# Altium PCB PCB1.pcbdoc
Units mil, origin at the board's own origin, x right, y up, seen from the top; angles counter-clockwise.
Board outline 2566.1 x 2465 mil, 4 copper layers (Top Layer, Inner1, Inner2, Bottom Layer); 31 components, 17 nets, 97 pads, 94 vias.
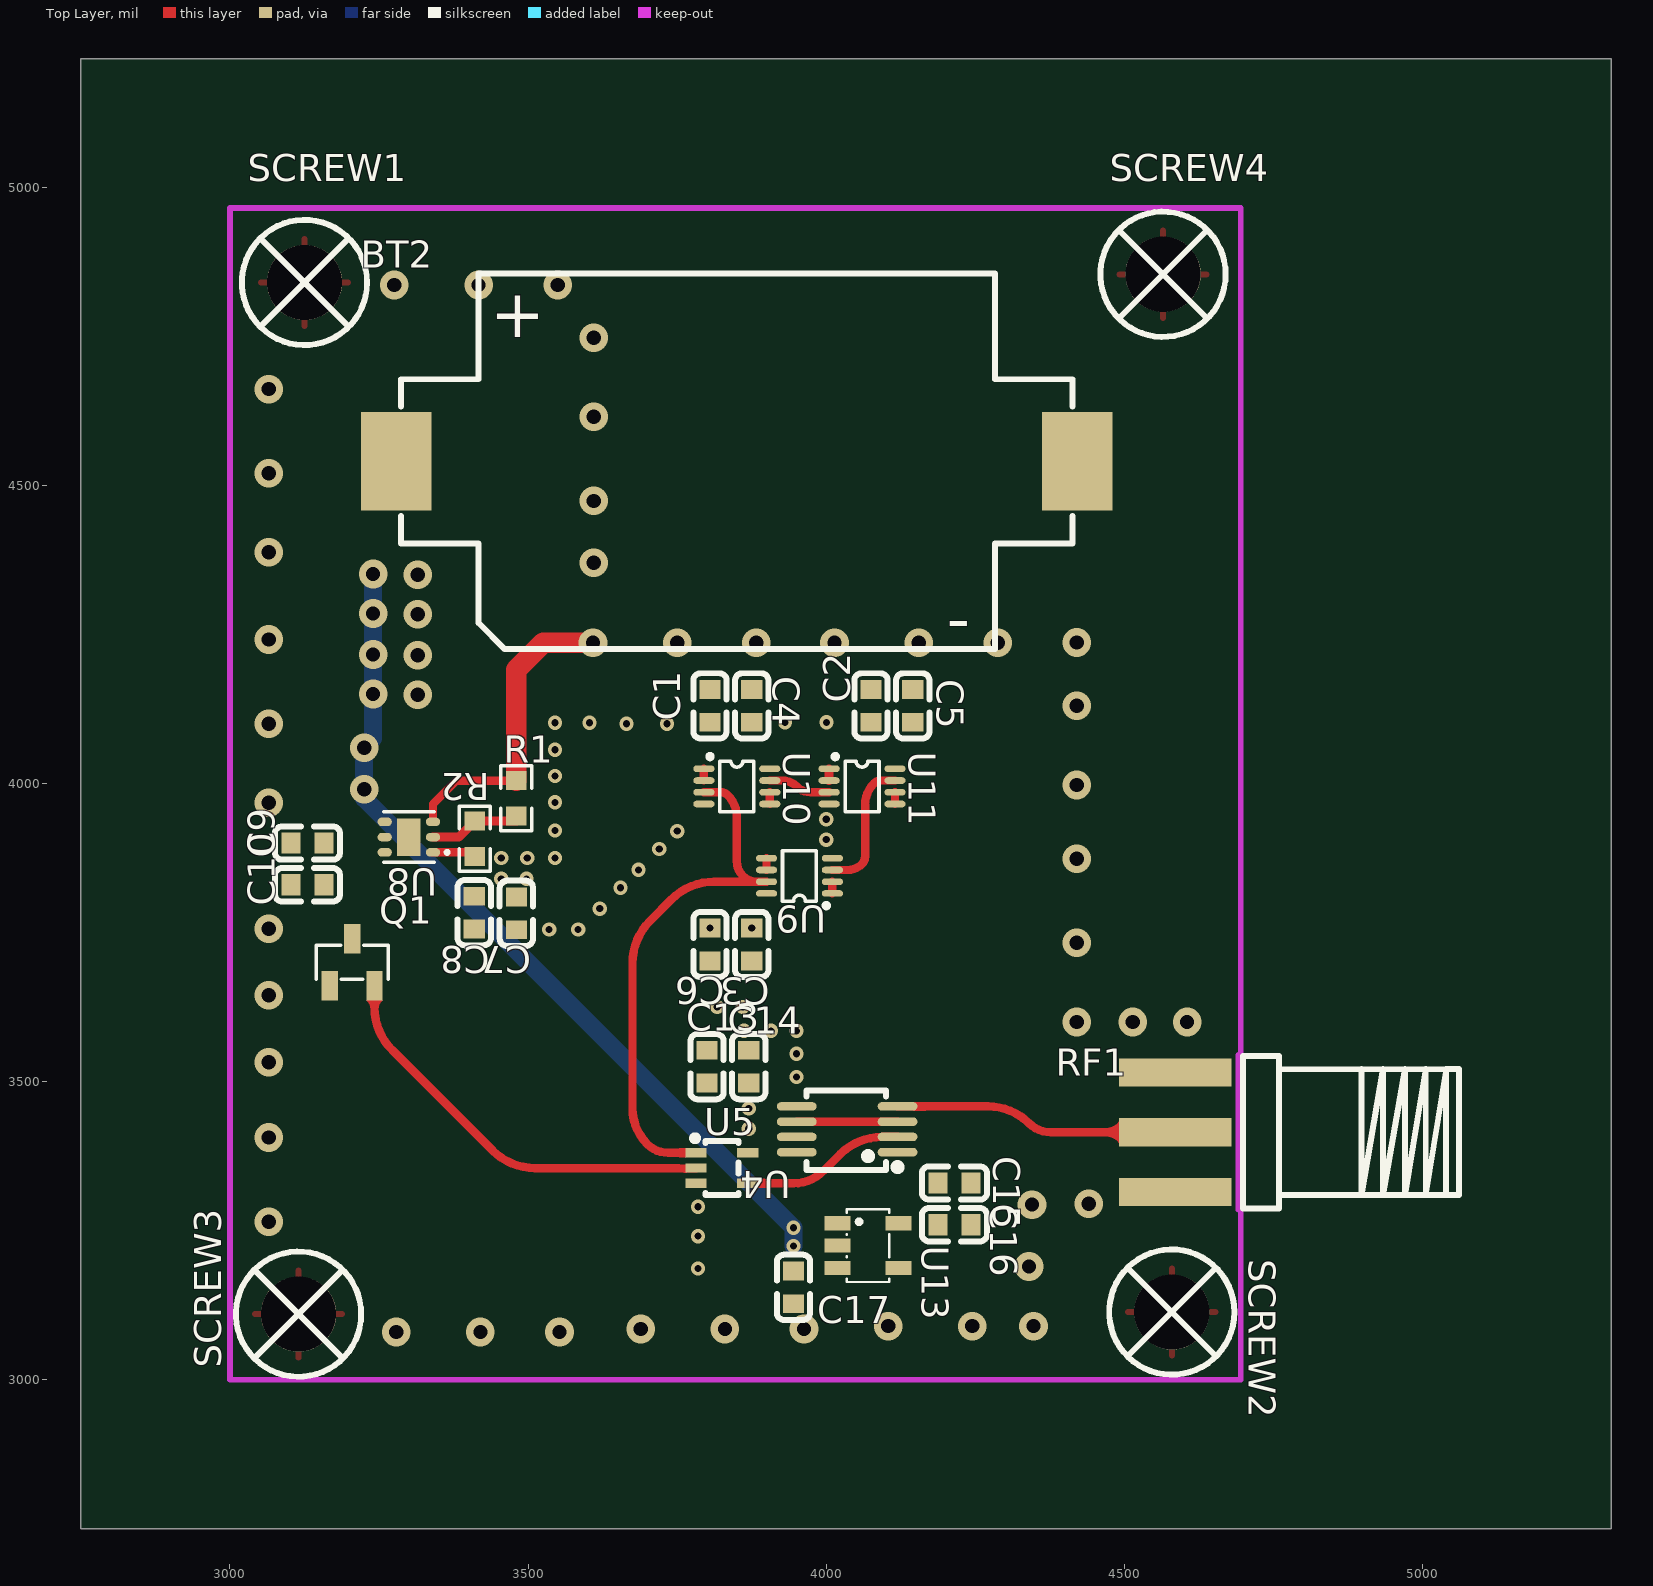
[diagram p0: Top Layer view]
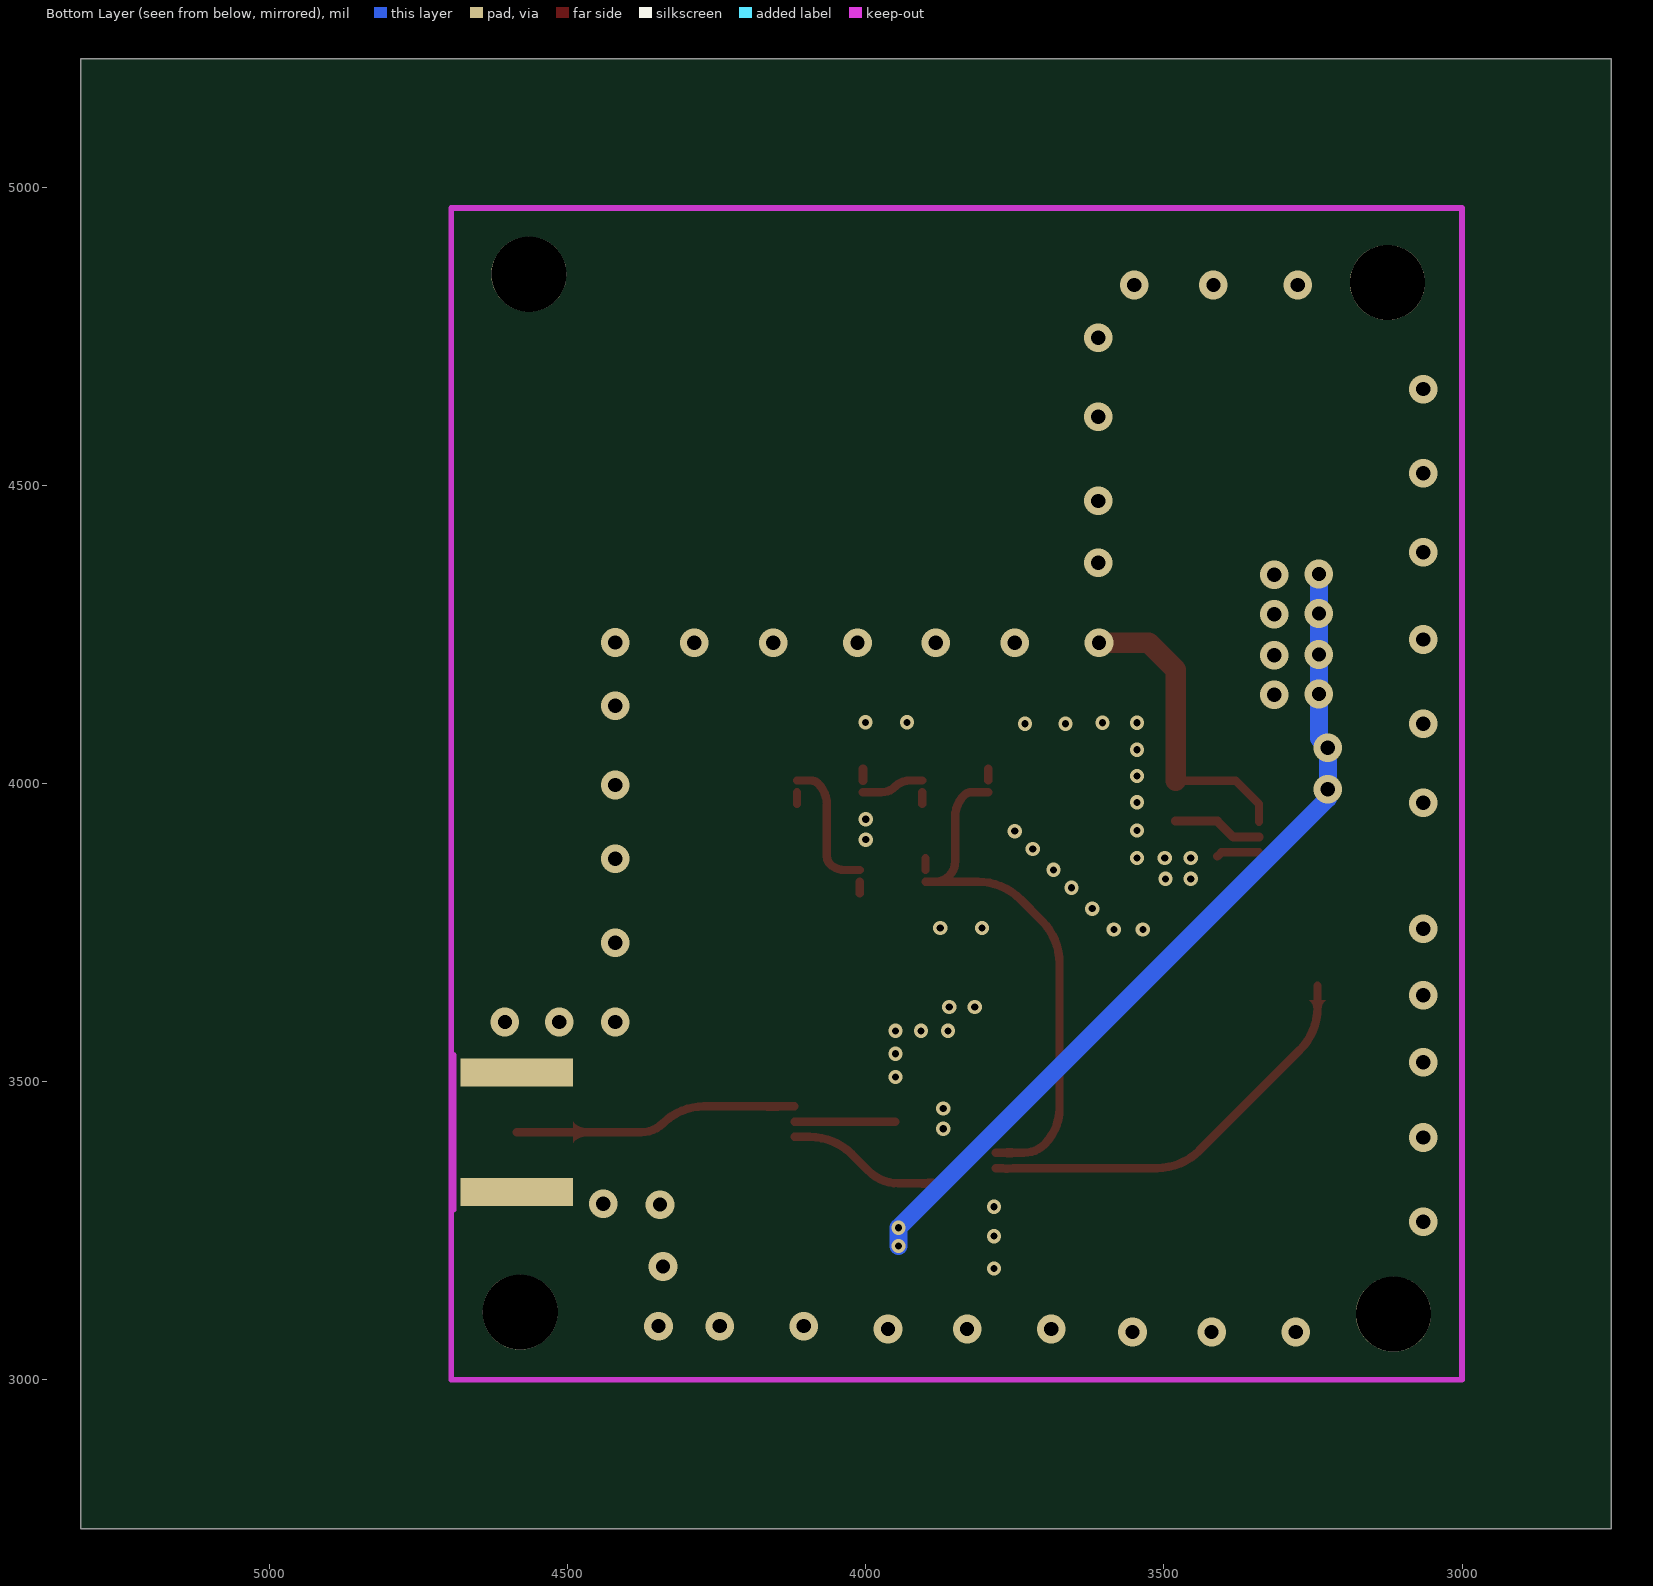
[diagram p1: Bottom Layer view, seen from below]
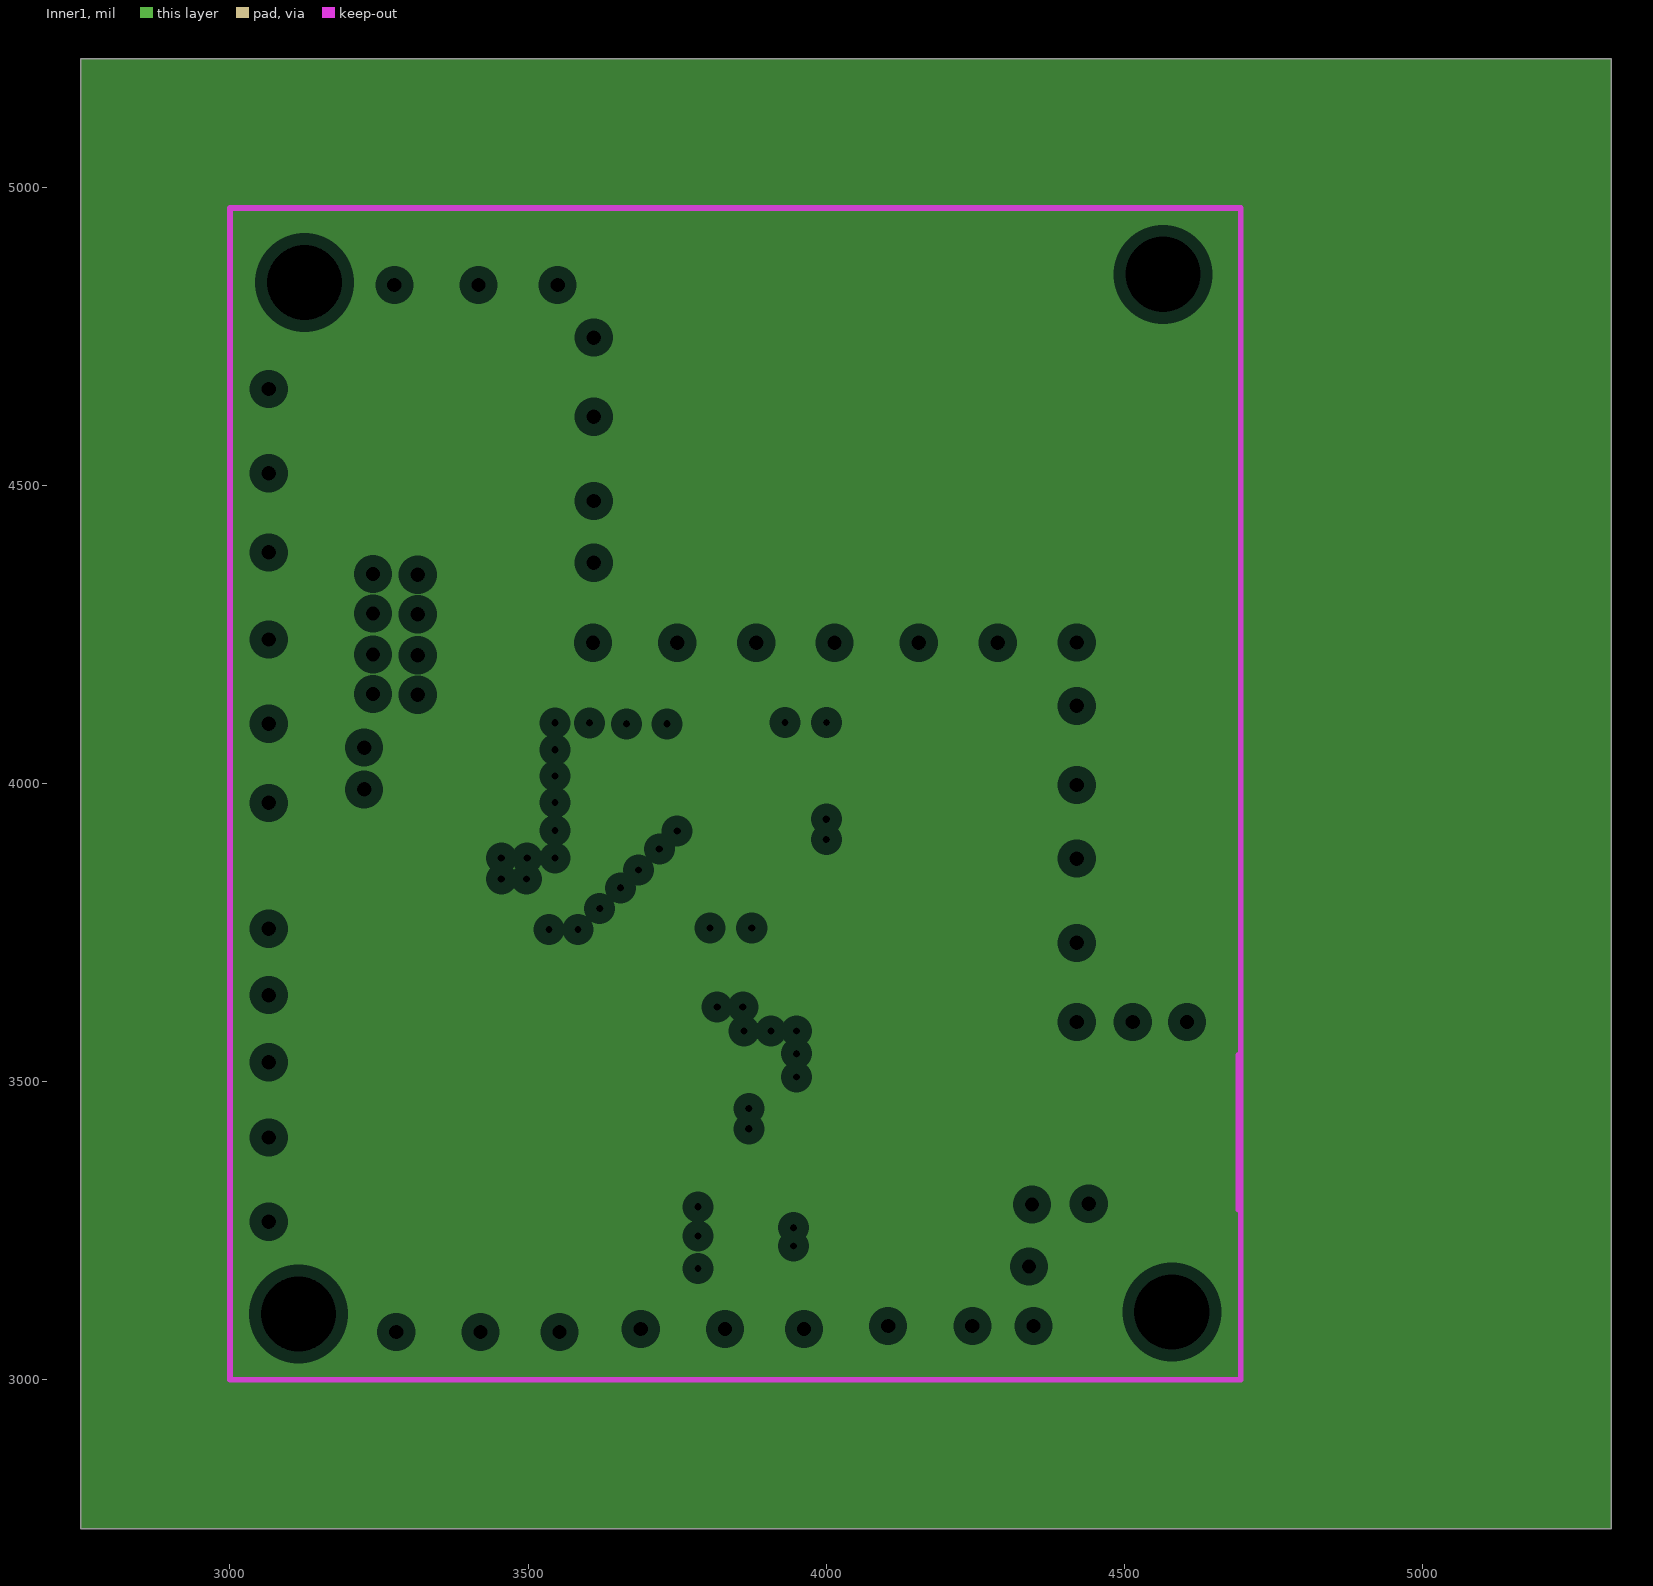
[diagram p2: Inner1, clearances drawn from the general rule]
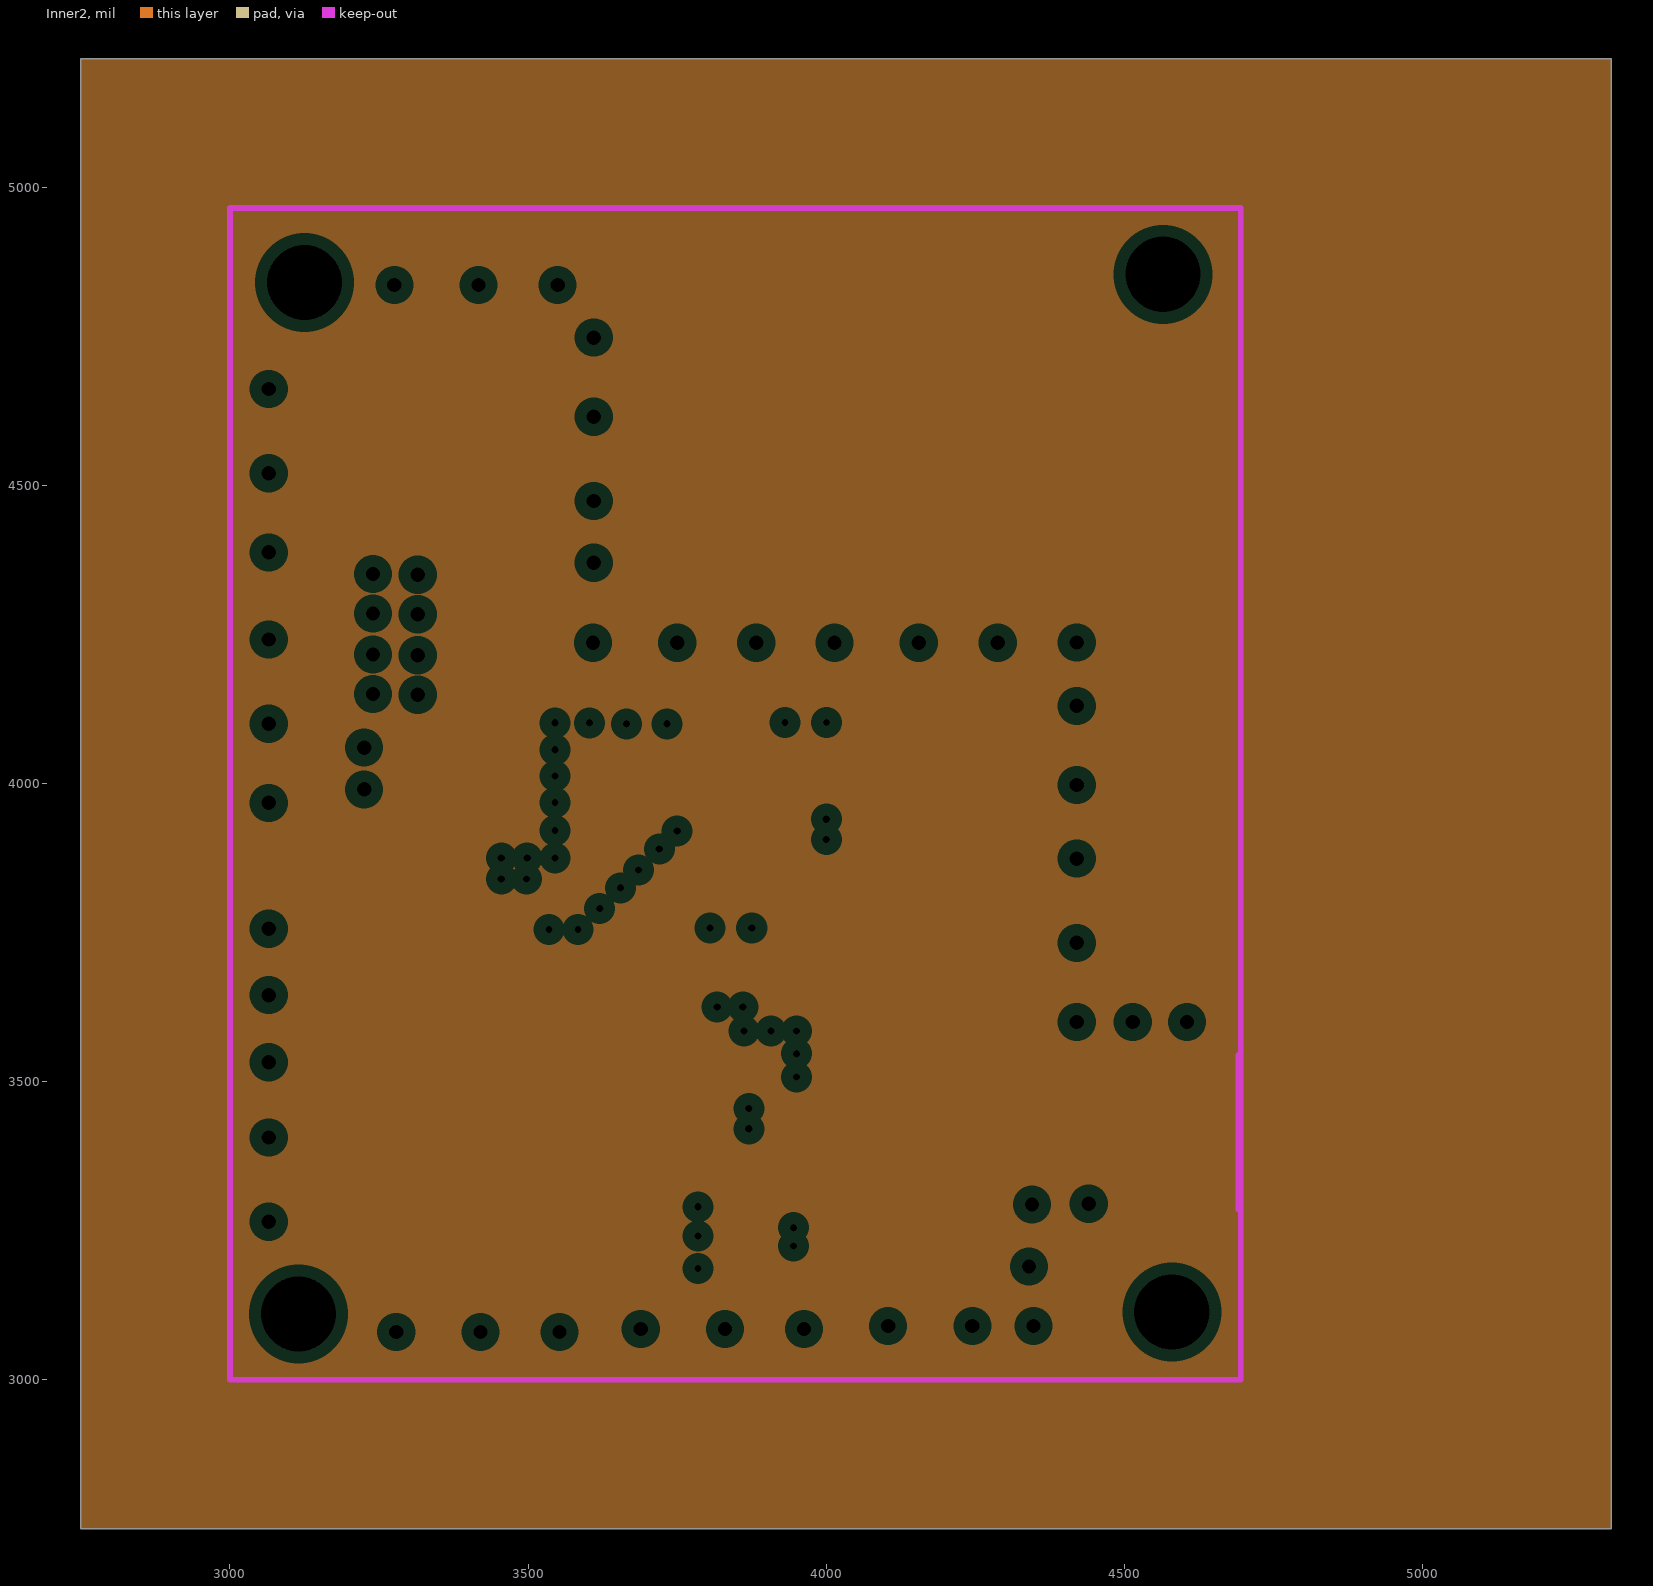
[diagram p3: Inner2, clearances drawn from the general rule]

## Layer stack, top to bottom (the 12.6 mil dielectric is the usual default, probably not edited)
Top Layer: signal copper (thickness not stored)
Dielectric: dielectric 12.6, FR-4, Dk 4.8
Inner1: plane copper (thickness not stored)
Dielectric: dielectric 12.6, FR-4, Dk 4.8
Inner2: plane copper (thickness not stored)
Dielectric: dielectric 12.6, FR-4, Dk 4.8
Bottom Layer: signal copper (thickness not stored)

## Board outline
5316.1,2750 2750,2750 2750,5215 5316.1,5215

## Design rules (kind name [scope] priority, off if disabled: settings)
BoardOutlineClearance copperThickness1oz [All] p0: genericclearance=10 ignorepadtopadclearanceinfootprint=FALSE except(0: Arc-SplitContinuation Track-SplitContinuation SMDPad-SplitContinuation THPad-SplitContinuation Via-SplitContinuation Fill-SplitContinuation Poly-SplitContinuation Region-SplitContinuation Text-SplitContinuation; 6: Track-CutoutEdge SMDPad-CutoutEdge THPad-CutoutEdge Via-CutoutEdge Region-CutoutEdge; 11.8: Track-OutlineEdge SMDPad-OutlineEdge THPad-OutlineEdge Via-OutlineEdge Fill-OutlineEdge Region-OutlineEdge Poly-OutlineEdge Text-OutlineEdge Fill-CutoutEdge)
BoardOutlineClearance copperThickness2oz [All] p0: genericclearance=10 ignorepadtopadclearanceinfootprint=FALSE except(0: Arc-SplitContinuation Track-SplitContinuation SMDPad-SplitContinuation THPad-SplitContinuation Via-SplitContinuation Fill-SplitContinuation Poly-SplitContinuation Region-SplitContinuation Text-SplitContinuation; 6: Track-CutoutEdge SMDPad-CutoutEdge THPad-CutoutEdge Via-CutoutEdge Region-CutoutEdge; 11.8: Track-OutlineEdge SMDPad-OutlineEdge THPad-OutlineEdge Via-OutlineEdge Fill-OutlineEdge Region-OutlineEdge Poly-OutlineEdge Text-OutlineEdge Fill-CutoutEdge)
Clearance copperThickness1oz [(InNet('+3V') OR InNet('GND') OR InNet('$1N1794') OR InNet('$1N1799') OR InNet('$1N1813') OR InNet('$1N1833') OR InNet('$1N1818') OR InNet('$1N1779') OR InNet('$1N1783') OR InNet('VCC') OR InNet('$1N2427') OR InNet('$1N2685') OR InNet('$1N2734') OR InNet('$1N2854') OR InNet('$1N5148') OR InNet('$1N5155') OR InNet('$1N5582'))] p1: gap=7 ignorepadtopadclearanceinfootprint=FALSE except(4: Track-Track; 6: Track-SMDPad SMDPad-SMDPad Track-THPad SMDPad-THPad THPad-THPad Track-Via SMDPad-Via THPad-Via Via-Via SMDPad-Fill THPad-Fill Via-Fill Fill-Fill Track-Region SMDPad-Region THPad-Region Via-Region Region-Region Track-Poly SMDPad-Poly THPad-Poly Via-Poly Fill-Poly Region-Poly Poly-Poly Track-Text SMDPad-Text THPad-Text Via-Text Fill-Text Region-Text Poly-Text Text-Text; 6.9: Track-Hole SMDPad-Hole THPad-Hole Via-Hole Fill-Hole Region-Hole Poly-Hole Text-Hole Sheet-Hole; 11.8: Track-Fill Fill-Region Track-Sheet SMDPad-Sheet THPad-Sheet Via-Sheet Fill-Sheet Region-Sheet Poly-Sheet Text-Sheet)
Clearance copperThickness2oz [All] p1: gap=7 ignorepadtopadclearanceinfootprint=FALSE except(6: Track-SMDPad SMDPad-SMDPad Track-THPad SMDPad-THPad THPad-THPad Track-Via SMDPad-Via THPad-Via Via-Via SMDPad-Fill THPad-Fill Via-Fill Fill-Fill Track-Region SMDPad-Region THPad-Region Via-Region Region-Region Track-Poly SMDPad-Poly THPad-Poly Via-Poly Fill-Poly Region-Poly Poly-Poly Track-Text SMDPad-Text THPad-Text Via-Text Fill-Text Region-Text Poly-Text Text-Text; 6.9: Track-Hole SMDPad-Hole THPad-Hole Via-Hole Fill-Hole Region-Hole Poly-Hole Text-Hole Sheet-Hole; 8: Track-Track; 11.8: Track-Fill Fill-Region Track-Sheet SMDPad-Sheet THPad-Sheet Via-Sheet Fill-Sheet Region-Sheet Poly-Sheet Text-Sheet)
DiffPairsRouting differentialPair [All] p1: maxuncoupledlength=10 minlimit=5.9843 maxlimit=5.9843 mostfreqgap=5.9843 toplayer_minwidth=5 toplayer_prefwidth=10 toplayer_maxwidth=100 bottomlayer_minwidth=5 bottomlayer_prefwidth=10 bottomlayer_maxwidth=100
PasteMaskExpansion pasteMaskExpansion [All] p1: expansion=0
PlaneConnect innerPlane [All] p1: planeconnectstyle=Relief reliefexpansion=20 reliefentries=4 reliefconductorwidth=10 reliefairgap=10
PolygonConnect copperRegion [All] p1: connectstyle=Direct reliefentries=4 reliefconductorwidth=10 polygonreliefangle="90 Angle" airgapwidth=10
RoutingVias viaSize [All] p1: viastyle="Through Hole" holewidth=12.0078 minholewidth=11.811 maxholewidth=248.0314 width=24.0158 minwidth=19.685 maxwidth=393.7008
SolderMaskExpansion solderMaskExpansion [All] p1: useseparateexpansions=TRUE expansion=2.0079 expansionbottom=2.0079
Width copperThickness1oz [All] p1: maxlimit=100 minlimit=5 preferedwidth=10
Width copperThickness2oz [All] p1: maxlimit=100 minlimit=8 preferedwidth=10

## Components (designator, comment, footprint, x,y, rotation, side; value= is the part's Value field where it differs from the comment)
BT2 "XDCR-2032-603" BAT-SMD_XDCR-2032-603 3850,4540 r0 top
C1 "CAP_0603" C0603 3805,4130 r90 top
C2 "CAP_0603" C0603 4075,4130 r90 top
C3 "CAP_0603" C0603 3875,3730 r270 top
C4 "CGA0603X5R105K500JT" C0603 3875,4130 r90 top
C5 "CGA0603X5R105K500JT" C0603 4145,4130 r90 top
C6 "CGA0603X5R105K500JT" C0603 3805,3730 r270 top
C7 "CAP_0603" C0603 3480.32,3782.19 r270 top
C8 "CGA0603X5R105K500JT" C0603 3409.64,3783.25 r270 top
C9 "CAP_0603" C0603 3130,3900 r0 top
C10 "CGA0603X5R105K500JT" C0603 3130,3830 r0 top
C13 "CAP_0603" C0603 3800,3525 r270 top
C14 "CGA0603X5R105K500JT" C0603 3870,3525 r270 top
C15 "CAP_0603" C0603 4215,3330 r180 top
C16 "CGA0603X5R105K500JT" C0603 4215,3260 r180 top
C17 "CAP_0603" C0603 3945,3155 r90 top
Q1 "MMBT3904_C7420353" SOT-23-3_L2.9-W1.3-P1.90-LS2.4-BR 3205,3700 r270 top
R1 "Res_0603" R0603 3480,3975 r270 top
R2 "Res_0603" R0603 3410.32,3907.19 r270 top
RF1 "BWSMA-KE-P001" SMA-SMD_BWSMA-KE-P001 4585,3415 r0 top
SCREW1 "M3螺丝" M3螺丝 3125,4840 r0 top
SCREW2 "M3螺丝" M3螺丝 4579.37,3113.47 r180 top
SCREW3 "M3螺丝" M3螺丝 3115,3110 r0 top
SCREW4 "M3螺丝" M3螺丝 4564.69,4853.78 r0 top
U4 "ADG902BRMZ" MSOP-8_L3.0-W3.0-P0.65-LS5.0-BL 4035,3420 r90 top
U5 "SN74AUP1G08DCKR(UMW)" SC-70-5_L2.1-W1.3-P0.65-LS2.2-BR 3825,3355 r180 top
U8 "TLV75801PDRVR" WSON-6_L2.0-W2.0-P0.65-TL-EP 3300,3910 r180 top
U9 "SN74AUP3G04DCUR" VSSOP-8_L2.3-W2.0-P0.50-LS3.1-BL 3955,3845 r90 top
U10 "SN74AUP3G04DCUR" VSSOP-8_L2.3-W2.0-P0.50-LS3.1-BL 3850,3995 r270 top
U11 "SN74AUP3G04DCUR" VSSOP-8_L2.3-W2.0-P0.50-LS3.1-BL 4060,3995 r270 top
U13 "TPS7A0518PDBVR" SOT-23-5_L3.0-W1.7-P0.95-LS2.8-BR 4070,3225 r180 top

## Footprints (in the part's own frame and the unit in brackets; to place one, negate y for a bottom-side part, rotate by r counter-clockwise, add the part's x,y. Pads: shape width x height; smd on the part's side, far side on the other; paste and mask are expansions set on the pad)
BAT-SMD_XDCR-2032-603 [mm]
  rect 3x4.2 smd: 1(-14.5,0) 2(14.5,0)
  silkscreen extent -14.3,-8 14.3,8
C0603 [mm]
  rect 0.8x0.9 smd: 1(-0.7,0) 2(0.7,0)
  silkscreen extent -1.39,-0.71 1.39,0.71
M3螺丝 [mil]
  round 126 hole 126: 1(0,0)
  silkscreen extent -105,-105 105,105
MSOP-8_L3.0-W3.0-P0.65-LS5.0-BL [mil]
  oval 14.33x66.61 smd: 1(-38.39,-84.49) 2(-12.79,-84.49) 3(12.8,-84.49) 4(38.39,-84.49) 5(38.39,84.49) 6(12.8,84.49) 7(-12.79,84.49) 8(-38.39,84.49)
  silkscreen extent -69,-90 65,68
R0603 [mil]
  rect 31.75x34.02 smd: 1(-29.66,0) 2(29.66,0)
  silkscreen extent -55,-26 55,26
SC-70-5_L2.1-W1.3-P0.65-LS2.2-BR [mm]
  rect 0.9x0.4 smd: 1(1.1,-0.65) 2(1.1,0) 3(1.1,0.65) 4(-1.1,0.65) 5(-1.1,-0.65)
  silkscreen extent -0.7,-1.4 1.27,1.15
SMA-SMD_BWSMA-KE-P001 [mm]
  rect 4.8x1.2 smd: 1(0,-2.55) 2(0,2.55) 5(0,0)
  rect 4.8x1.2 smd far side: 3(0,2.55) 4(0,-2.55)
  Board Outline Layer lines w0.254: 2.7,-3.3 2.7,3.3 2.7,-3.3
  silkscreen extent 2.89,-3.25 12.1,3.25
SOT-23-3_L2.9-W1.3-P1.90-LS2.4-BR [mm]
  rect 1.25x0.7 smd: 1(1,-0.95) 2(1,0.95) 3(-1,0)
  silkscreen extent -0.73,-1.53 0.73,1.53
SOT-23-5_L3.0-W1.7-P0.95-LS2.8-BR [mm]
  rect 1.1x0.6 smd: 1(1.3,-0.95) 2(1.3,0) 3(1.3,0.95) 4(-1.3,0.95) 5(-1.3,-0.95)
  silkscreen extent -0.9,-1.55 0.9,1.55
VSSOP-8_L2.3-W2.0-P0.50-LS3.1-BL [mm]
  oval 0.28x0.905 smd: 1(-0.75,-1.403) 2(-0.25,-1.403) 3(0.25,-1.403) 4(0.75,-1.403) 5(0.75,1.403) 6(0.25,1.403) 7(-0.25,1.403) 8(-0.75,1.403)
  silkscreen extent -1.37,-1.24 1.08,0.72
WSON-6_L2.0-W2.0-P0.65-TL-EP [mm]
  oval 0.607x0.364 smd: 1(-1.028,0.65) 2(-1.028,0) 3(-1.028,-0.65) 4(1.028,-0.65) 5(1.028,0) 6(1.028,0.65)
  rect 1x1.6 smd: 7(0,0)
  silkscreen extent -1.71,-1.08 1.08,1.08

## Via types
v1: diameter 48, hole 24, Top Layer to Bottom Layer, 54 vias
v2: diameter 24.02, hole 12.01, Top Layer to Bottom Layer, 40 vias

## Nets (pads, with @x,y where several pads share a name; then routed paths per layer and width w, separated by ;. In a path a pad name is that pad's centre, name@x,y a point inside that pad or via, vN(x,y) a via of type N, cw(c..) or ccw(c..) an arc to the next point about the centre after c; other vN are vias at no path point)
$1N1779: U10.1 U10.2 | length 19.7
  Top Layer w14.1: U10.2 U10.1
$1N1783: U10.5 U10.6 | length 19.7
  Top Layer w14.1: U10.5 U10.6
$1N1794: U9.1 U9.2 | length 19.7
  Top Layer w14.1: U9.1 U9.2
$1N1799: U9.5 U9.6 | length 19.7
  Top Layer w14.1: U9.6 U9.5
$1N1813: U11.1 U11.2 | length 19.7
  Top Layer w15: U11.2 U11.1
$1N1818: U11.5 U11.6 | length 19.7
  Top Layer w14.1: U11.5 U11.6
$1N1833: U10.7 U11.3 | length 104.8
  Top Layer w14.1: U10.7 3926.24,4004.84 cw(c3926.24,3971.24) 3950,3995 ccw(c3973.76,4018.76) 3973.76,3985.16 U11.3
$1N2427: R1.2 R2.1 U8.2 | length 151
  Top Layer w15: U8.2 3383.47,3910 R2.1 R1.2@3480.32,3936.85
$1N2685: Q1.2 U5.2 | length 703.2
  Top Layer w14.1: Q1.2 3242.4,3624.02 ccw(c3342.4,3624.02) 3271.69,3553.31 3440.71,3384.29 ccw(c3511.42,3455) 3511.42,3355 3739.36,3355 ccw(c3742.82,3373.54) 3742.82,3354.68 cw(c3742.82,3101.69) 3762.51,3353.91 ccw(c3763.97,3372.71) 3770.45,3355 U5.2
$1N2734: U4.2 U5.4 | length 276.1
  Top Layer w14.1: U5.4 3945.29,3329.41 ccw(c3945.29,3399.71) 3995,3350 4022.92,3377.92 cw(c4093.63,3307.21) 4093.63,3407.21 U4.2
$1N2854: RF1.5 U4.4 | length 477.1
  Top Layer w14.1: U4.4 4271.46,3458.39 cw(c4271.46,3361.46) 4340,3430 ccw(c4376.2,3466.2) 4376.2,3415.01 RF1.5
$1N5148: U5.1 U9.7 U10.3 | length 902.5
  Top Layer w14.1: U5.1 3734.79,3380.59 cw(c3734.79,3429.79) 3700,3395 cw(c3760.36,3455.36) 3675,3455.36 3675,3698.58 cw(c3775,3698.58) 3704.29,3769.29 3740.87,3805.87 cw(c3811.58,3735.16) 3811.58,3835.16 U9.7@3883.76,3835.16 ; U10.3 3822.54,3985.16 cw(c3822.54,3967.54) 3835,3980 cw(c3798.79,3943.79) 3850,3943.79 3850,3869.14 ccw(c3884.14,3869.14) 3860,3845 ccw(c3883.76,3868.76) U9.7@3883.76,3835.16 ; U9.7 U9.7@3883.76,3835.16
$1N5155: U9.3 U11.7 | length 229.4
  Top Layer w14.1: U9.3 4035.47,3854.84 ccw(c4035.47,3889.53) 4060,3865 ccw(c4047.93,3877.07) 4065,3877.07 4065,3963.79 cw(c4116.21,3963.79) 4080,4000 cw(c4091.68,3988.32) 4091.68,4004.84 U11.7
$1N5582: C15.2 C16.2 U4.1 U13.5
+3V: BT2.1 C9.2 C10.2 C17.2 Q1.1 U8.4 U8.6 U13.1 U13.3 | length 1431.4
  Bottom Layer w30: v1(3240,4351.16) v1(3240,4285) v1(3240,4216.16) v1(3240,4150) 3240,4075 v1(3225,4060) v1(3225,3990) 3225,3975 v2(3945,3255) v2(3945,3224.16)
  other v1: 3315,4148.73 3315,4215 3315,4283.73 3315,4350
GND: BT2.2 C1.2 C2.2 C3.2 C4.2 C5.2 C6.2 C7.2 C8.2 C9.1 C10.1 C13.1 C14.1 C15.1 C16.1 C17.1 Q1.3 R1.1 RF1.1 RF1.2 RF1.3 RF1.4 SCREW1.1 SCREW2.1 SCREW3.1 SCREW4.1 U4.3 U4.5 U4.6 U4.7 U4.8 U5.3 U8.3 U9.4 U10.4 U11.4 U13.2 | length 687.8
  Top Layer w14.1: U8.3 3340.49,3965.49 3379.66,4004.66 R1.1 ; U4.6 U4.3
  Top Layer w35: R1.1 3480,4190 3525.98,4235.98 v1(3608.76,4235.98)
  other v1: 3278.73,3080 3420,3080 3552.57,3080 3688.73,3085 3830,3085 3962.57,3085 4103.73,3090 4245,3090 4347.57,3090 4340,3190 3065,3265 4345,3293.73 4440,3295 3065,3406.27 3065,3532.43 4420,3600 4513.97,3600 4605,3600 3065,3645 4420,3732.57 3065,3756.27 4420,3873.84 3065,3967.43 4420,3997.43 3065,4100 4420,4130 3750.03,4235.98 3882.6,4235.98 4013.76,4235.98 4155.03,4235.98 4287.6,4235.98 4420,4236.27 3065,4241.27 3610,4370 3065,4387.43 3610,4473.73 3065,4520 3610,4615 3065,4661.27 3610,4747.57 3275.67,4835.73 3416.93,4835.73 3549.51,4835.73
  other v2: 3785,3186.48 3785,3240.85 3785,3290 3950,3507.56 3950,3546.75 3862.04,3585 3907.26,3585 3950,3585 3817.01,3625 3860,3625 3535.17,3755 3583.81,3755 3620,3790 3655,3825 3685,3855 3720,3890 4000,3905.77 3750,3920 4000,3940
VCC: C1.1 C2.1 C3.1 C4.1 C5.1 C6.1 C7.1 C8.1 C13.2 C14.2 R2.2 U5.5 U8.1 U9.8 U10.8 U11.8 | length 72.7
  Top Layer w14.1: U8.1 3403.44,3884.41 R2.2
  other v2: 3870,3420.85 3870,3455 3805,3757.56 3875,3757.56 3455,3840 3497.27,3840 3455,3875 3498.46,3875 3545,3875 3545,3921.12 3545,3968.17 3545,4012.58 3545,4056.45 3665,4100 3732.78,4100 3545,4101.63 3602.92,4101.63 3930.84,4102.44 4000.27,4102.44
pads on no net: U8.5 U8.7 U13.4

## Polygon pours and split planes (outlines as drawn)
GND on Bottom Layer (solid, remove dead copper, pour order 56): 4385,3340 4385,3290 4550,3290 4555,3295 4555,3320 4535,3340
GND on Bottom Layer (solid, remove dead copper, pour order 54): 4490,3625 4490,3515 4641.45,3515 4641.45,3618.55 4635,3625
GND on Top Layer (solid, remove dead copper, pour order 2): 3555,4815 3555,4140 4500,4140 4500,4730 4405,4825 3565,4825
GND on Top Layer (solid, remove dead copper, pour order 26): 3975,3870 4027.86,3870 4027.86,3970.8 3981.14,3970.8 3975,3964.66
GND on Top Layer (solid, remove dead copper, pour order 24): 3800,3330 3800,3095 3775,3120 3765,3120 3765,3330
VCC on Top Layer (solid, remove dead copper, pour order 22): 3850,3375 3850,3479.83 3780.17,3479.83 3780,3480 3780,3510 3785,3515 3885,3515 3890,3510 3890,3380 3885,3375
GND on Top Layer (solid, remove dead copper, pour order 0): 4225,3340 4680,3340 4685,3335 4685,3015 4690,3010 3010,3010 3005,3015 3005,4955 3010,4960 4670,4960 4690,4940 4690,3495 4695,3490 4380,3490 4370,3490.08 4370,4780 3175.25,4780 3125,4729.75 3125,3250 3225,3150 4225,3150
GND on Top Layer (solid, remove dead copper, pour order 18): 3920,3380 3985,3380 3985,3615 3875,3615 3870,3620 3870,3536.95 3920,3536.95
GND on Top Layer (solid, remove dead copper, pour order 16): 3780,3535 3785,3540 3785,3720 3890,3720 3895,3715 3895,3536.03 3893.97,3535
VCC on Top Layer (solid, remove dead copper, pour order 14): 3455,3895 3565,3895 3570,3900 3570,3799.95 3475.05,3799.95 3455,3820
VCC on Top Layer (solid, remove dead copper, pour order 12): 3393.59,3892.62 3393.9,3875.57 3393.9,3796.81 3493.19,3796.81 3495,3795 3495,3894.5
+3V on Top Layer (solid, remove dead copper, pour order 6): 3190,3940 3190,4650 3355,4650 3365,4640 3365,4090 3265,4090 3265,3940
+3V on Top Layer (solid, remove dead copper, pour order 4): 3270,3925 3270,3952.37 3192.37,3952.37 3190,3950 3190,3865 3265,3865 3270,3870 3270,3893.61 3227.96,3893.61 3227.96,3926.33 3268.67,3926.33
VCC on Top Layer (solid, remove dead copper, pour order 30): 4172.94,4120 4172.94,4078.85 3638.85,4078.85 3570,4010 3570,3850 3525,3850 3525,4120
VCC on Top Layer (solid, remove dead copper, pour order 32): 3885,4025 3885,4049.52 3847.04,4087.47 3961.94,4087.47 3925,4050.53 3925,4025
VCC on Top Layer (solid, remove dead copper, pour order 36): 4135,4025 4135,4053.11 4169.36,4087.48 4053.25,4087.48 4093.4,4053.31 4093.4,4026.6 4095,4025
VCC on Top Layer (solid, remove dead copper, pour order 40): 3785.39,3772.52 3840.01,3772.52 3880,3812.51 3880,3820 3918.84,3820 3918.84,3741.51 3786.51,3741.51 3785,3740 3785,3772.13
GND on Top Layer (solid, remove dead copper, pour order 44): 3770,3970 3809.81,3970 3810,3965 3810,3950.44 3589.56,3730 3565,3730 3565,3765
GND on Top Layer (solid, remove dead copper, pour order 46): 4055,3210 4055,3124.61 4086.34,3124.61 4086.34,3238.19 3995,3238.19 3995,3210
+3V on Top Layer (solid, remove dead copper, pour order 48): 3917.06,3198.66 4040.4,3198.66 4040.4,3171.03 3917.06,3171.03
+3V on Top Layer (solid, remove dead copper, pour order 50): 4040,3275 4040,3250 3970,3250 3970,3181.78 3926.78,3181.78 3920,3175 3920,3275.7 4039.3,3275.7
$1N5582 on Top Layer (solid, remove dead copper, pour order 52): 4085,3380 4085,3250 4203.44,3250 4203.44,3349.05 4151.65,3349.05 4151.65,3381.19 4086.19,3381.19
GND on Top Layer (solid, remove dead copper, pour order 54): 3385.26,3732.1 3504.68,3732.1 3504.68,3771.16 3383.84,3771.16 3380,3775 3380,3737.36
+3V on Top Layer (solid, remove dead copper, pour order 60): 3140.99,3810 3141.03,3811.03 3141.03,3918.43 3197.6,3975 3200,3975 3200,3871.56 3263.44,3871.56 3270,3865 3245,3840 3245,3810
+3V on Top Layer (solid, remove dead copper, pour order 64): 3140.97,3830 3140.97,3635 3177.73,3635 3177.73,3830
GND on Top Layer (solid, remove dead copper, pour order 66): 3190,3770 3500,3770 3505,3765 3505,3731.04 3236.04,3731.04 3220,3715 3189.43,3715 3189.43,3769.43
GND on Top Layer (solid, remove dead copper, pour order 68): 3589.34,3731.04 3472.83,3731.04 cw(c3472.83,3740.39) 3466.22,3733.78 ccw(c3432.18,3767.82) 3480.32,3767.82 3480.32,3768.44 3599.91,3768.44 3599.91,3756.57 cw(c3563.81,3756.57)

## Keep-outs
Board Outline Layer:
  lines w10: 3000,3000 4695,3000 4695,4965 3000,4965 3000,3000

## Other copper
Top Layer:
  region net $1N2854: 4469.37,3407.95 4469.37,3422.05 ccw(c4469.37,3448.49) 4490.52,3432.63 4490.52,3397.38 ccw(c4469.37,3381.52)
  region net $1N2854: 4166.78,3465.44 4166.78,3451.34 4145.63,3451.22 4145.63,3465.56
  region net $1N2734: 3907.18,3336.46 3907.18,3322.36 ccw(c3907.18,3050.51) 3886.03,3321.53 3886.03,3337.28 ccw(c3907.18,3608.3)
  region net $1N5148: 3742.82,3373.54 3742.82,3387.64 ccw(c3742.82,3659.48) 3763.97,3388.46 3763.97,3372.71 ccw(c3742.82,3101.69)
  region net $1N2685: 3249.45,3624.02 3235.35,3624.02 ccw(c3221.28,3624.02) 3228.62,3636.02 3256.18,3636.02 ccw(c3263.52,3624.02)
